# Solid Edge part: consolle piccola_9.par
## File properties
Last saved by: i.fialdini
Revision: 62
Tipo di contenuto documento: 0
Accuracy: 0.990
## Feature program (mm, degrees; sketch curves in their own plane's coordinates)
body "unnamed Body 1"
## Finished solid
Body 1: solid body, 12 faces, 30 edges, 20 vertices.
  Faces by surface: plane 8, cylinder 4
  Edges by curve: line 22, circle 8
Bounding box of the edges (mm): 52.500 x 416.000 x 2.000, from (187, -924.1568, 700.9818) to (239.5, -508.1568, 702.9818).
Cylindrical faces by radius (mm): R5 x2, R30.5 x2
Planar faces by outward normal: +x 2, +y 1, +z 1, -x 2, -y 1, -z 1
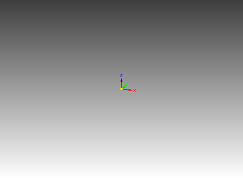
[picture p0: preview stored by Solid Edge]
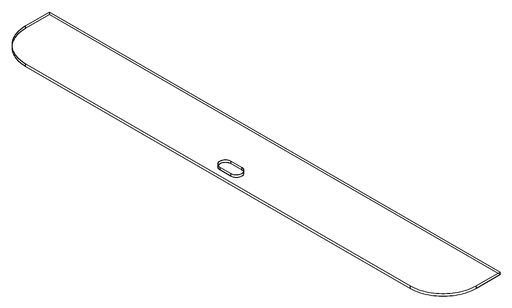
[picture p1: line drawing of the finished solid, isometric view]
